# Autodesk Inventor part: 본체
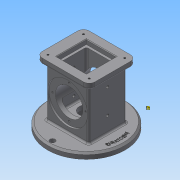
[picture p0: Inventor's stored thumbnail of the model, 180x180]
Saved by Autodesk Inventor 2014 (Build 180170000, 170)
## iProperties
Created: 2019-08
Part Number: 본체
Material: 일반
Document SubType Name: Modeling
Designer: NET
Density: 1 g/cm^3
Appearance: 기본값
Author: NET
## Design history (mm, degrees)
sketch "스케치1"
  geometry: L1 (37, -33)-(-37, -33); L2 (-37, -33)-(-37, 33); L3 (-37, 33)-(37, 33); L4 (37, 33)-(37, -33); L5 (37, -33)-(-37, 33); L6 (-37, -33)-(37, 33); 1 further point
  constraints: 12 end point, 2 midpoint, 2 parallel, 1 horizontal, 1 perpendicular
  dimensions: "d0" = 74 distance of L2.end L3.end; "d1" = 66 distance of L3.end L1.start
extrude "돌출1" new body sketch "스케치1" distance "d2" = 108; taper "d3" = 0 deg
node "작업 평면1"
sketch "스케치2"
  geometry: L1 (-33, 0)-(-33, 108) reference; L2 (33, 0)-(33, 108) reference; L3 (33, 0)-(33, 108) reference; L4 (-33, 54)-(33, 54); L5 (-33, 0)-(33, 0) reference; L6 (-33, 89)-(-30, 89); L7 (-30, 89)-(-30, 78); L8 (-30, 78)-(30, 78); L9 (30, 78)-(30, 89); L10 (30, 89)-(33, 89); 1 further point
  constraints: 12 end point, 3 parallel, 3 perpendicular, 2 midpoint, 2 point on line, 1 collinear
  dimensions: "d4" = 54 distance between parallel lines of L5 L4; "d5" = 70 diameter of L6 L4; "d6" = 48 diameter of L8 L4; "d7" = 70 diameter of L10 L4; "d8" = 3 distance of L6.start L6.end
revolve "회전1" sketch "스케치2" stored, may be unused: angle "d9" = 90 deg
sketch "스케치3"
  geometry: L1 (26, 26)-(-26, 26); L2 (-26, 26)-(-26, -26); L3 (-26, -26)-(26, -26); L4 (26, -26)-(26, 26); L5 (26, 26)-(-26, -26); L6 (-26, 26)-(26, -26); L7 (22, 22)-(-22, 22); L8 (-22, 22)-(-22, -22); L9 (-22, -22)-(22, -22); L10 (22, -22)-(22, 22); L11 (22, 22)-(-22, -22); L12 (-22, 22)-(22, -22); 1 further point
  constraints: 24 end point, 4 midpoint, 4 parallel, 3 perpendicular, 2 horizontal, 1 point on line
  dimensions: "d10" = 52 distance of L1.end L2.end; "d11" = 44 distance of L7.end L8.end
extrude "돌출2" cut sketch "스케치3" distance "d12" = 8; taper "d13" = 0 deg
extrude "돌출3" cut sketch "스케치3" distance "d14" = 82; taper "d15" = 0 deg
node "작업 평면2"
sketch "스케치4"
  geometry: C1 r 25 at (0, 0); C2 r 12.5 at (0, 0); 1 further point
  constraints: 2 centre point, 2 coincident
  dimensions: "d16" = 50 diameter of C1; "d17" = 25 diameter of C2
extrude "돌출4" cut sketch "스케치4" distance "d18" = 18; taper "d19" = 0 deg
extrude "돌출5" cut sketch "스케치4" stored distance "d20" = 18; taper "d21" = 0 deg
sketch "스케치5"
  geometry: C1 r 67.5 at (0, 0); 1 further point
  constraints: 1 centre point, 1 coincident
  dimensions: "d22" = 135 diameter of C1
extrude "돌출6" join sketch "스케치5" distance "d23" = 10; taper "d24" = 0 deg
sketch "스케치6"
  geometry: C1 r 12.5 at (0, 0) reference; C2 r 12.5 at (0, 0)
  constraints: 1 centre point, 1 coincident, 1 concentric
extrude "돌출7" cut sketch "스케치6" distance "d25" = 10; taper "d26" = 0 deg
sketch "스케치7"
  geometry: L1 (-37, -33)-(37, -33) reference; L2 (37, -33)-(37, 33) reference; L3 (37, 33)-(-37, 33) reference; L4 (-37, 33)-(-37, -33) reference; L5 (46, -41)-(-46, -41); L6 (-46, -41)-(-46, 41); L7 (-46, 41)-(46, 41); L8 (46, 41)-(46, -41); L9 (46, -41)-(-46, 41); L10 (-46, -41)-(46, 41); 1 further point
  constraints: 12 end point, 2 midpoint, 2 parallel, 1 horizontal, 1 perpendicular
  dimensions: "d27" = 82 distance of L7.end L5.start; "d28" = 92 distance of L6.end L7.end
extrude "돌출8" join sketch "스케치7" distance "d29" = 10; taper "d30" = 0 deg
sketch "스케치8"
  geometry: L1 (36, -31)-(-36, -31); L2 (-36, -31)-(-36, 31); L3 (-36, 31)-(36, 31); L4 (36, 31)-(36, -31); L5 (36, -31)-(-36, 31); L6 (-36, -31)-(36, 31); 5 further points
  constraints: 12 end point, 4 coincident, 2 midpoint, 2 parallel, 1 horizontal, 1 perpendicular
  dimensions: "d31" = 72 distance of L2.end L3.end; "d32" = 62 distance of L3.end L1.start
hole "구멍1" sketch "스케치8" diameter "d33" = 3.242; stored, may be unused: countersink angle "d37" = 90 deg, drill point angle "d39" = 118 deg; dims "d34" = 4, "d35" = 4, "d36" = 2, "d38" = 6
hole "구멍2" sketch "스케치8" diameter "d43" = 3.242; stored, may be unused: countersink angle "d47" = 90 deg, drill point angle "d49" = 118 deg; dims "d44" = 4, "d45" = 4, "d46" = 2, "d48" = 6
hole "구멍3" sketch "스케치8" diameter "d50" = 3.242; stored, may be unused: countersink angle "d54" = 90 deg, drill point angle "d56" = 118 deg; dims "d51" = 4, "d52" = 4, "d53" = 2, "d55" = 6
hole "구멍4" sketch "스케치8" diameter "d57" = 3.242; stored, may be unused: countersink angle "d61" = 90 deg, drill point angle "d63" = 118 deg; dims "d58" = 4, "d59" = 4, "d60" = 2, "d62" = 6
sketch "스케치9"
  geometry: L1 (-88, 74)-(-88, -8) reference; L2 (10, -34.5)-(10, 100.5) reference; 4 further points
  constraints: 4 horizontal alignment, 1 midpoint
  dimensions: "d64" = 37 distance from line of L2 point (-27, 33); "d65" = 43 distance of point (-27, 33) point (-70, 33)
hole "구멍5" sketch "스케치9" at (-70, 33), (-27, 33) diameter "d66" = 4.917; stored, may be unused: countersink angle "d70" = 90 deg, drill point angle "d72" = 118 deg; dims "d67" = 4, "d68" = 4, "d69" = 2, "d71" = 6
sketch "스케치10" dims "d73" = 58
  geometry: C1 r 35 at (0, 0) reference; C2 r 24 at (0, 0) reference; 3 further points
  constraints: 2 vertical alignment, 1 coincident, 2 other
hole "구멍6" sketch "스케치10" at (0, 29) diameter "d74" = 3.242; stored, may be unused: countersink angle "d78" = 90 deg, drill point angle "d80" = 118 deg; dims "d75" = 4, "d76" = 4, "d77" = 2, "d79" = 6
node "작업 평면3"
sketch "스케치11"
  geometry: 1 further point
sketch "스케치12"
  geometry: C1 r 67.5 at (0, 0) reference; C2 r 4.5 at (-59, 0); C3 r 4.5 at (0, 59); C4 r 4.5 at (0, -59); A1 r 59 centre (0, 0) between (-59, 0) and (0, 59)
  constraints: 4 centre point, 3 point on circle, 2 vertical alignment, 1 coincident, 1 horizontal alignment
  dimensions: "d85" = 118 diameter of A1; "d86" = 9 diameter of C2; "d87" = 9 diameter of C4; "d88" = 9 diameter of C3
extrude "돌출9" cut sketch "스케치12" stored distance "d89" = 10; taper "d90" = 0 deg
chamfer "모따기1" distance "d91" = 3; stored, may be unused: second distance "d92" = 2, angle "d93" = 45 deg
chamfer "모따기2" distance "d94" = 1; stored, may be unused: second distance "d95" = 2, angle "d96" = 45 deg
fillet "모깎기1" dims "d97" = 3
fillet "모깎기2" dims "d98" = 3
fillet "모깎기3" dims "d99" = 3
sketch "스케치13"
  geometry: 1 further point
sketch "스케치14"
  geometry: C1 r 12.5 at (0, 0) reference; C2 r 67.5 at (0, 0) reference; C3 r 25 at (0, 0)
  constraints: 1 centre point, 1 coincident
  dimensions: "d100" = 50 diameter of C3
extrude "돌출10" cut sketch "스케치14" distance "d101" = 18; taper "d102" = 0 deg
fillet "모깎기4" dims "d103" = 3
fillet "모깎기5" dims "d104" = 3
fillet "모깎기6" dims "d105" = 3
fillet "모깎기7" dims "d106" = 10
fillet "모깎기8" dims "d107" = 3
node "작업 평면4"
sketch "스케치15"
  geometry: 1 further point
fillet "모깎기9" dims "d109" = 3
sketch "스케치17"
  geometry: C1 r 64.5 at (0, 0) reference; C2 r 59 at (0, 0)
  constraints: 1 centre point, 1 coincident, 1 other
  dimensions: "d110" = 118 diameter of C2
feature "엠보싱1" sketch "스케치17" dims "d111" = 0.5, "d112" = 0
node "솔리드1"
pattern_linear "직사각형 패턴1" dims "d42" = 72
pattern_circular "원형 패턴1" dims angle "d82" = 360 deg
mirror "대칭1"
